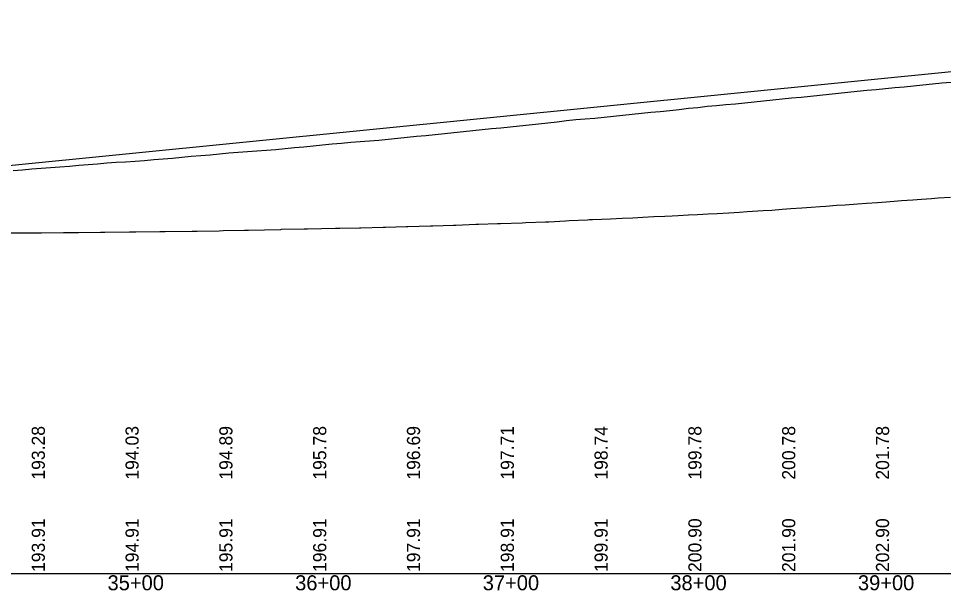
# Model space of a CAD drawing. Extents: x 1876258 to 1932803, y 754739 to 837911.
# Drawn here: x 1880098 to 1880591.1, y 820541 to 820846.1 of the extents above; entities that cross this region are included whole.
import ezdxf

# ---------------------------------------------------------------- set-up
doc = ezdxf.new("R2010")
doc.units = 0
for name, color, linetype in [('RD_DDB_Profile_EX', 7, 'Continuous'), ('RD_DDB_Profile_PR', 7, 'Continuous'), ('RD_DDB_StaTX', 7, 'Continuous'), ('RD_DDB_StripGrade', 7, 'Continuous'), ('RD_GPK_Profile_Cell', 7, 'Continuous'), ('RD_Sketch1', 7, 'Continuous')]:
    doc.layers.add(name, color=color, linetype=linetype)

msp = doc.modelspace()

# ---------------------------------------------------------------- linework, layer by layer
at = {"layer": 'RD_DDB_Profile_EX'}
for points in [[(1880390.15, 820791.63), (1880395.15, 820792.14), (1880400.15, 820792.55), (1880405.15, 820793), (1880410.15, 820793.5), (1880415.15, 820794.03), (1880420.15, 820794.52), (1880425.15, 820795), (1880430.15, 820795.55), (1880435.15, 820796.06), (1880440.15, 820796.55), (1880445.15, 820797.07), (1880450.15, 820797.63), (1880455.15, 820798.18), (1880460.15, 820798.71), (1880465.15, 820799.27), (1880470.15, 820799.75), (1880475.15, 820800.17), (1880480.15, 820800.6), (1880485.15, 820801.08), (1880490.15, 820801.58), (1880495.15, 820802.13), (1880500.15, 820802.69), (1880505.15, 820803.23), (1880510.15, 820803.74), (1880515.15, 820804.21), (1880520.15, 820804.7), (1880525.15, 820805.19), (1880530.15, 820805.68), (1880535.15, 820806.2), (1880540.15, 820806.79), (1880545.15, 820807.34), (1880550.15, 820807.83), (1880555.15, 820808.29), (1880560.15, 820808.73), (1880565.15, 820809.23), (1880570.15, 820809.72), (1880575.15, 820810.2), (1880580.15, 820810.69), (1880585.15, 820811.21), (1880590.15, 820811.74), (1880595.15, 820812.2)], [(1880095.15, 820765.01), (1880100.15, 820765.42), (1880105.15, 820765.85), (1880110.15, 820766.3), (1880115.15, 820766.66), (1880120.15, 820767.02), (1880125.15, 820767.42), (1880130.15, 820767.79), (1880135.15, 820768.19), (1880140.15, 820768.64), (1880145.15, 820769.05), (1880150.15, 820769.41), (1880155.15, 820769.68), (1880160.15, 820769.99), (1880165.15, 820770.44), (1880170.15, 820770.84), (1880175.15, 820771.23), (1880180.15, 820771.67), (1880185.15, 820772.16), (1880190.15, 820772.61), (1880195.15, 820773.01), (1880200.15, 820773.42), (1880205.15, 820773.93), (1880210.15, 820774.36), (1880215.15, 820774.76), (1880220.15, 820775.1), (1880225.15, 820775.43), (1880230.15, 820775.78), (1880235.15, 820776.22), (1880240.15, 820776.68), (1880245.15, 820777.21), (1880250.15, 820777.72), (1880255.15, 820778.25), (1880260.15, 820778.74), (1880265.15, 820779.21), (1880270.15, 820779.67), (1880275.15, 820780.07), (1880280.15, 820780.46), (1880285.15, 820780.86), (1880290.15, 820781.27), (1880295.15, 820781.75), (1880300.15, 820782.26), (1880305.15, 820782.76), (1880310.15, 820783.26), (1880315.15, 820783.77), (1880320.15, 820784.27), (1880325.15, 820784.77), (1880330.15, 820785.27), (1880335.15, 820785.79), (1880340.15, 820786.3), (1880345.15, 820786.82), (1880350.15, 820787.34), (1880355.15, 820787.85), (1880360.15, 820788.36), (1880365.15, 820788.87), (1880370.15, 820789.38), (1880375.15, 820789.9), (1880380.15, 820790.46), (1880385.15, 820791.04), (1880390.15, 820791.63)]]:
    msp.add_lwpolyline(points, dxfattribs=at)
at = {"layer": 'RD_DDB_Profile_PR'}
msp.add_line((1880091.08, 820767.49), (1880878.08, 820846.1), dxfattribs=at)
at = {"layer": 'RD_GPK_Profile_Cell'}
msp.add_line((1878363.08, 820550.13), (1884763.08, 820550.13), dxfattribs=at)
at = {"layer": 'RD_Sketch1'}
msp.add_lwpolyline([(1880093.9, 820731.71), (1880106.12, 820731.85), (1880110.27, 820731.86), (1880121.99, 820731.93), (1880125.85, 820731.96), (1880129.95, 820731.96), (1880141.66, 820732.06), (1880144.02, 820732.17), (1880157.16, 820732.33), (1880160.61, 820732.34), (1880173.32, 820732.52), (1880176.21, 820732.55), (1880190.66, 820732.7), (1880193.26, 820732.73), (1880204.93, 820732.9), (1880207.05, 820732.94), (1880218.56, 820733.18), (1880220.54, 820733.22), (1880237.61, 820733.63), (1880237.91, 820733.64), (1880238.21, 820733.65), (1880250.3, 820733.85), (1880252.1, 820733.88), (1880252.14, 820733.88), (1880267.08, 820734.19), (1880267.24, 820734.19), (1880267.39, 820734.2), (1880269.37, 820734.22), (1880279.79, 820734.39), (1880280.48, 820734.41), (1880292.37, 820734.84), (1880293.65, 820734.86), (1880304.65, 820735.2), (1880305.62, 820735.23), (1880317.6, 820735.49), (1880318.83, 820735.53), (1880329.89, 820735.92), (1880331.08, 820735.95), (1880341.86, 820736.37), (1880343.31, 820736.39), (1880353.3, 820736.74), (1880355, 820736.79), (1880366.56, 820737.16), (1880368.44, 820737.22), (1880378.91, 820737.66), (1880380.63, 820737.73), (1880389.68, 820738.22), (1880391.63, 820738.35), (1880401.24, 820738.77), (1880402.43, 820738.81), (1880404.07, 820738.88), (1880413.65, 820739.29), (1880419.74, 820739.57), (1880425.5, 820739.85), (1880430.88, 820740.11), (1880436.69, 820740.41), (1880442.59, 820740.69), (1880446.45, 820740.85), (1880449.73, 820741.07), (1880455.12, 820741.31), (1880459.96, 820741.54), (1880465.63, 820741.88), (1880470.49, 820742.12), (1880476.72, 820742.48), (1880482.31, 820742.86), (1880486.48, 820743.17), (1880489.23, 820743.37), (1880494.93, 820743.63), (1880499.63, 820743.93), (1880505.01, 820744.36), (1880509.66, 820744.76), (1880515.61, 820745.12), (1880520.64, 820745.46), (1880525.38, 820745.83), (1880528.37, 820746.05), (1880534.09, 820746.46), (1880538.72, 820746.75), (1880545.26, 820747.24), (1880550.07, 820747.59), (1880555.83, 820748.01), (1880560.61, 820748.34), (1880564.71, 820748.67), (1880568.63, 820749), (1880574.75, 820749.41), (1880579.29, 820749.69), (1880584.75, 820750.1), (1880588.33, 820750.36), (1880594.87, 820750.73)], dxfattribs=at)
msp.add_lwpolyline([(1880093.9, 820731.71), (1880106.12, 820731.85), (1880110.27, 820731.86), (1880121.99, 820731.93), (1880125.85, 820731.96), (1880129.95, 820731.96), (1880141.66, 820732.06), (1880144.02, 820732.17), (1880157.16, 820732.33), (1880160.61, 820732.34), (1880173.32, 820732.52), (1880176.21, 820732.55), (1880190.66, 820732.7), (1880193.26, 820732.73), (1880204.93, 820732.9), (1880207.05, 820732.94), (1880218.56, 820733.18), (1880220.54, 820733.22), (1880237.61, 820733.63), (1880237.91, 820733.64), (1880238.21, 820733.65), (1880250.3, 820733.85), (1880252.1, 820733.88), (1880252.14, 820733.88), (1880267.08, 820734.19), (1880267.24, 820734.19), (1880267.39, 820734.2), (1880269.37, 820734.22), (1880279.79, 820734.39), (1880280.48, 820734.41), (1880292.37, 820734.84), (1880293.65, 820734.86), (1880304.65, 820735.2), (1880305.62, 820735.23), (1880317.6, 820735.49), (1880318.83, 820735.53), (1880329.89, 820735.92), (1880331.08, 820735.95), (1880341.86, 820736.37), (1880343.31, 820736.39), (1880353.3, 820736.74), (1880355, 820736.79), (1880366.56, 820737.16), (1880368.44, 820737.22), (1880378.91, 820737.66), (1880380.63, 820737.73), (1880389.68, 820738.22), (1880391.63, 820738.35), (1880401.24, 820738.77), (1880402.43, 820738.81), (1880404.07, 820738.88), (1880413.65, 820739.29), (1880419.74, 820739.57), (1880425.5, 820739.85), (1880430.88, 820740.11), (1880436.69, 820740.41), (1880442.59, 820740.69), (1880446.45, 820740.85), (1880449.73, 820741.07), (1880455.12, 820741.31), (1880459.96, 820741.54), (1880465.63, 820741.88), (1880470.49, 820742.12), (1880476.72, 820742.48), (1880482.31, 820742.86), (1880486.48, 820743.17), (1880489.23, 820743.37), (1880494.93, 820743.63), (1880499.63, 820743.93), (1880505.01, 820744.36), (1880509.66, 820744.76), (1880515.61, 820745.12), (1880520.64, 820745.46), (1880525.38, 820745.83), (1880528.37, 820746.05), (1880534.09, 820746.46), (1880538.72, 820746.75), (1880545.26, 820747.24), (1880550.07, 820747.59), (1880555.83, 820748.01), (1880560.61, 820748.34), (1880564.71, 820748.67), (1880568.63, 820749), (1880574.75, 820749.41), (1880579.29, 820749.69), (1880584.75, 820750.1), (1880588.33, 820750.36), (1880594.87, 820750.73)], dxfattribs=at)
msp.add_lwpolyline([(1880093.9, 820731.71), (1880106.12, 820731.85), (1880110.27, 820731.86), (1880121.99, 820731.93), (1880125.85, 820731.96), (1880129.95, 820731.96), (1880141.66, 820732.06), (1880144.02, 820732.17), (1880157.16, 820732.33), (1880160.61, 820732.34), (1880173.32, 820732.52), (1880176.21, 820732.55), (1880190.66, 820732.7), (1880193.26, 820732.73), (1880204.93, 820732.9), (1880207.05, 820732.94), (1880218.56, 820733.18), (1880220.54, 820733.22), (1880237.61, 820733.63), (1880237.91, 820733.64), (1880238.21, 820733.65), (1880250.3, 820733.85), (1880252.1, 820733.88), (1880252.14, 820733.88), (1880267.08, 820734.19), (1880267.24, 820734.19), (1880267.39, 820734.2), (1880269.37, 820734.22), (1880279.79, 820734.39), (1880280.48, 820734.41), (1880292.37, 820734.84), (1880293.65, 820734.86), (1880304.65, 820735.2), (1880305.62, 820735.23), (1880317.6, 820735.49), (1880318.83, 820735.53), (1880329.89, 820735.92), (1880331.08, 820735.95), (1880341.86, 820736.37), (1880343.31, 820736.39), (1880353.3, 820736.74), (1880355, 820736.79), (1880366.56, 820737.16), (1880368.44, 820737.22), (1880378.91, 820737.66), (1880380.63, 820737.73), (1880389.68, 820738.22), (1880391.63, 820738.35), (1880401.24, 820738.77), (1880402.43, 820738.81), (1880404.07, 820738.88), (1880413.65, 820739.29), (1880419.74, 820739.57), (1880425.5, 820739.85), (1880430.88, 820740.11), (1880436.69, 820740.41), (1880442.59, 820740.69), (1880446.45, 820740.85), (1880449.73, 820741.07), (1880455.12, 820741.31), (1880459.96, 820741.54), (1880465.63, 820741.88), (1880470.49, 820742.12), (1880476.72, 820742.48), (1880482.31, 820742.86), (1880486.48, 820743.17), (1880489.23, 820743.37), (1880494.93, 820743.63), (1880499.63, 820743.93), (1880505.01, 820744.36), (1880509.66, 820744.76), (1880515.61, 820745.12), (1880520.64, 820745.46), (1880525.38, 820745.83), (1880528.37, 820746.05), (1880534.09, 820746.46), (1880538.72, 820746.75), (1880545.26, 820747.24), (1880550.07, 820747.59), (1880555.83, 820748.01), (1880560.61, 820748.34), (1880564.71, 820748.67), (1880568.63, 820749), (1880574.75, 820749.41), (1880579.29, 820749.69), (1880584.75, 820750.1), (1880588.33, 820750.36), (1880594.87, 820750.73)], dxfattribs=at)

# ---------------------------------------------------------------- texts
at = {"layer": 'RD_DDB_StaTX'}
for s, p in [('35+00', (1880145.49, 820541.13)), ('36+00', (1880245.49, 820541.13)), ('37+00', (1880345.49, 820541.13)), ('38+00', (1880445.49, 820541.13)), ('39+00', (1880545.49, 820541.13))]:
    msp.add_text(s, height=8, dxfattribs=at).set_placement(p)
at = {"layer": 'RD_DDB_StripGrade'}
for s, p in [('193.28', (1880112.08, 820600.13)), ('194.03', (1880162.08, 820600.13)), ('194.89', (1880212.08, 820600.13)), ('195.78', (1880262.08, 820600.13)), ('196.69', (1880312.08, 820600.13)), ('197.71', (1880362.08, 820600.13)), ('198.74', (1880412.08, 820600.13)), ('199.78', (1880462.08, 820600.13)), ('200.78', (1880512.08, 820600.13)), ('201.78', (1880562.08, 820600.13)), ('193.91', (1880112.08, 820550.88)), ('194.91', (1880162.08, 820550.88)), ('195.91', (1880212.08, 820550.88)), ('196.91', (1880262.08, 820550.88)), ('197.91', (1880312.08, 820550.88)), ('198.91', (1880362.08, 820550.88)), ('199.91', (1880412.08, 820550.88)), ('200.90', (1880462.08, 820550.88)), ('201.90', (1880512.08, 820550.88)), ('202.90', (1880562.08, 820550.88))]:
    msp.add_text(s, height=7, rotation=90, dxfattribs=at).set_placement(p)

doc.saveas('drawing.dxf')
